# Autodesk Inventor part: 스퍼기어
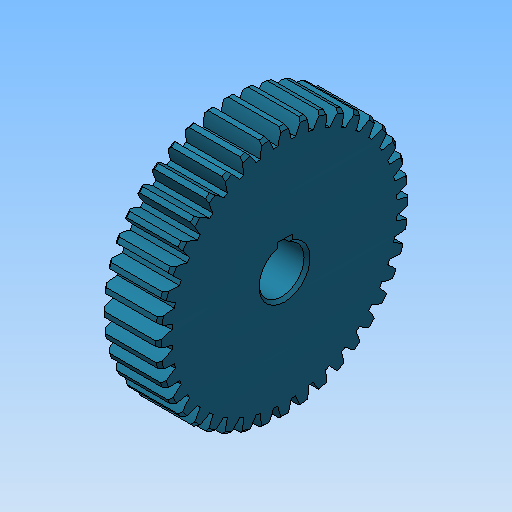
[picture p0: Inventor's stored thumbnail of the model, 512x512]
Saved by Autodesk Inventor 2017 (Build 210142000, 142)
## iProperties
Created: 2018-11
Part Number: 스퍼기어
Material: 알루미늄 6061
Document SubType Name: Modeling
Designer: mduedu
Categories: <?xml version="1.0" encoding="UTF-16"?> <MemberInstance><Categories><FamilyTemplate><FamilyTemplateParameter ValueType="xs:double" Id="1" ObjectReferenceKey="da
Density: 1 g/cm^3
Appearance: 터키옥색
CustomPartVersion: 1
Author: mduedu
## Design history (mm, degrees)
sketch "Sketch1"
  geometry: C1 r 42 at (0, 0)
  constraints: 1 centre point
  dimensions: "d0" = 83.99905 diameter of C1 (= da_da)
extrude "Extrusion1" new body sketch "Sketch1" distance "d1" = 19 (= da_b); taper "d2" = 0 deg
workplane "Work Plane2"
sketch "Sketch2"
  geometry: C1 r 42 at (0, 0) reference; C2 r 40.05 at (0, 0)
  constraints: 1 centre point, 1 coincident
  dimensions: "d3" = 80.10038 diameter of C2 (= da_dw)
feature "피치 지름" sketch "Sketch2" dims "d4" = 10, "d5" = 0
workplane "Work Plane8"
workplane "Work Plane9"
feature "스퍼 기어" dims "da_b" = 19, "da_d" = 80, "da_aw" = 80.10038, "da_da" = 83.99905, "da_df" = 75, "da_dw" = 80.10038, angle "da_beta" = 0 deg, "da_lefttooth" = 0, "da_righttooth" = 0
sketch "스케치3"
  geometry: L1 (-42, 19)-(42, 19) reference; L2 (42, 19)-(42, 0) reference; L3 (42, 0)-(-42, 0) reference; L4 (-42, 0)-(-42, 19) reference; L5 (0, 0)-(0, 19); L6 (42, 0)-(41, 0); L7 (42, 1)-(42, 0); L8 (42, 19)-(41, 19); L9 (42, 18)-(42, 19); L10 (41, 19)-(42, 18); L11 (41, 0)-(42, 1)
  constraints: 14 end point, 2 horizontal, 2 vertical, 1 midpoint
  dimensions: "d49" = 1 distance from line of L8.end L2; "d50" = 1 horizontal distance of L8.end L9.start; "d51" = 1 horizontal distance of L6.end L7.start; "d52" = 1 horizontal distance of L6.end L7.start
revolve "회전1" sketch "스케치3" stored, may be unused: angle "d53" = 90 deg
sketch "스케치4"
  geometry: L1 (-2.5, 7.071)-(2.5, 7.071); L2 (2.5, 7.071)-(2.5, 9.8); L3 (2.5, 9.8)-(-2.5, 9.8); L4 (-2.5, 9.8)-(-2.5, 7.071); A1 r 7.5 centre (0, 0) between (-2.5, 7.071) and (2.5, 7.071); 1 further point
  constraints: 8 end point, 2 parallel, 2 point on circle, 1 centre point, 1 coincident, 1 horizontal, 1 perpendicular
  dimensions: "d54" = 15 diameter of A1; "d56" = 17.3 dimension on A1 L3; "d57" = 5 distance of L2.end L3.end
extrude "돌출2" cut sketch "스케치4" stored distance "d58" = 10; taper "d59" = 0 deg
chamfer "모따기1" distance "d60" = 1; stored, may be unused: second distance "d61" = 2, angle "d62" = 45 deg
sketch "스케치5"
  geometry: C1 r 17.5 at (0, 0); C2 r 28.5 at (0, 0); 1 further point
  constraints: 2 centre point, 2 coincident
  dimensions: "d63" = 35 diameter of C1; "d64" = 57 diameter of C2
extrude "돌출3" cut sketch "스케치5" distance "d65" = 9.5; taper "d66" = 0 deg
fillet "모깎기1" dims "d67" = 3
chamfer "모따기2" distance "d68" = 0.5; stored, may be unused: second distance "d69" = 2, angle "d70" = 45 deg
body "Solid1"
body "Srf1"
node "절단 모서리 투영1"
other parameters: "d16" = 80.10038 (= da_aw), "d17" = 0, "d34" = 4.5 deg (computed from da_z), "d39" = 0, "d41" = 0, "d43" = 80.10038 (= da_aw), "d46" = 80.10038 (= da_aw), "d47" = 0, "d48" = 0
